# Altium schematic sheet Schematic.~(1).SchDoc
size A0; SheetNumber: 1; SheetTotal: 1
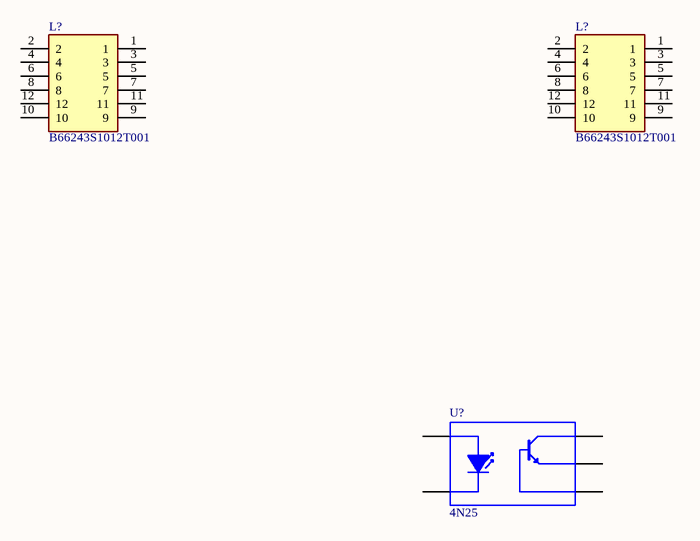
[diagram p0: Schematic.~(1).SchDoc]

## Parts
(Parts that share a designator on the sheet are numbered #1, #2 ... from top to bottom, then left to right.)
L?#1  B66243S1012T001  [B66243S1012T001]
L?#2  B66243S1012T001  [B66243S1012T001]
U?  4N25  [DIP6]

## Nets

Not connected (* = marked no-connect by the designer): L?#1 1 2 3 4 5 6 7 8 9 10 11 12; L?#2 1 2 3 4 5 6 7 8 9 10 11 12; U? 1(A) 2(K) 4(E) 5(C) 6(B)

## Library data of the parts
L?#1 L?#2 = B66243S1012T001: Ferrite Accessories, Planar Cores Accessories(E/ELP), Coil former (E 42/21/20); Manufacturer_Name: TDK; Geometry.Height: 41mm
